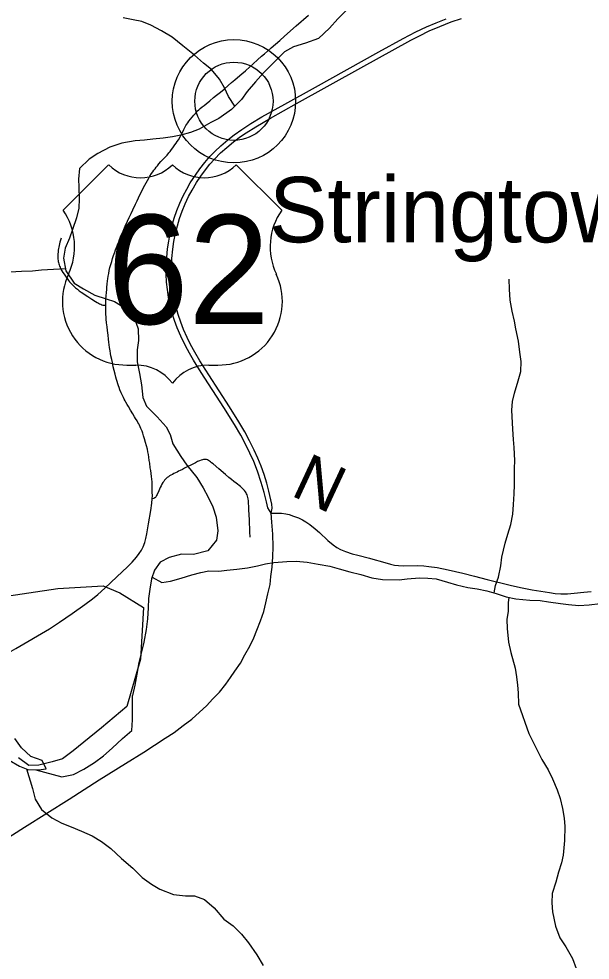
# Model space of a CAD drawing. Extents: x 0 to 34, y 0 to 22.
# Drawn here: x 5.89 to 6.579, y 17.482 to 18.618 of the extents above; entities that cross this region are included whole.
import ezdxf

# ---------------------------------------------------------------- set-up
doc = ezdxf.new("R2010")
doc.units = 0
for name, color, linetype in [('GM_X_Corporation', 7, 'Continuous'), ('GM_X_County_Road', 7, 'Continuous'), ('GM_X_County_Road_Text', 7, 'Continuous'), ('GM_X_Major_River', 7, 'Continuous'), ('GM_X_Minor_River', 7, 'Continuous'), ('GM_X_Township_Road', 7, 'Continuous'), ('GM_X_Unincorporated', 7, 'Continuous'), ('GM_X_Unincorporated_Location', 7, 'Continuous'), ('GM_X_Unincorporated_Text', 7, 'Continuous'), ('GM_X_US_Location', 7, 'Continuous'), ('GM_X_US_Route', 7, 'Continuous'), ('GM_X_US_Shield', 7, 'Continuous')]:
    doc.layers.add(name, color=color, linetype=linetype)

msp = doc.modelspace()

# ---------------------------------------------------------------- linework, layer by layer
at = {"layer": 'GM_X_Corporation'}
msp.add_lwpolyline([(5.6566, 17.8886), (5.9367, 17.9306), (5.9914, 17.934), (6.0115, 17.9254), (6.0403, 17.9078), (6.0367, 17.8455), (6.0202, 17.7883), (5.9894, 17.7625), (5.9681, 17.7452), (5.9552, 17.7349), (5.9426, 17.7251), (5.9299, 17.7214), (5.9138, 17.7172), (5.9017, 17.7169), (5.8892, 17.7264)], dxfattribs=at)
at = {"layer": 'GM_X_County_Road'}
for points in [[(5.9948, 18.2724), (5.9948, 18.2754), (5.9949, 18.2795), (5.9951, 18.2838), (5.9954, 18.2877), (5.9958, 18.2915), (5.996, 18.2943), (5.9964, 18.2981), (5.9968, 18.3018), (5.9971, 18.3045), (5.9976, 18.3077), (5.9982, 18.3109), (5.9989, 18.3146), (5.9996, 18.3179), (6.0007, 18.3217), (6.0018, 18.3253), (6.0029, 18.3289), (6.0041, 18.3325), (6.0055, 18.3364), (6.0065, 18.3393), (6.0075, 18.3423), (6.0087, 18.3455), (6.0102, 18.3492), (6.0113, 18.352), (6.0125, 18.355), (6.0138, 18.3579), (6.0156, 18.362), (6.0182, 18.3679), (6.0208, 18.3738), (6.0229, 18.3784), (6.0251, 18.3831), (6.0273, 18.3876), (6.0305, 18.3943), (6.0324, 18.3983), (6.0342, 18.402), (6.0359, 18.4057), (6.038, 18.4102), (6.0402, 18.4144), (6.0417, 18.4173), (6.0434, 18.4204), (6.0449, 18.4232), (6.0464, 18.4258), (6.048, 18.4284), (6.0499, 18.4315), (6.0513, 18.4334), (6.0527, 18.4355), (6.0541, 18.4372), (6.0555, 18.439), (6.057, 18.4408), (6.0588, 18.443), (6.0612, 18.4458), (6.0632, 18.4481), (6.0662, 18.4514), (6.0686, 18.4538), (6.0709, 18.4564), (6.0724, 18.4582), (6.074, 18.4604), (6.0756, 18.4626), (6.0781, 18.4661), (6.0795, 18.4681), (6.0809, 18.4702), (6.0822, 18.4723), (6.0845, 18.4759), (6.0861, 18.479), (6.0875, 18.4819), (6.0888, 18.4846), (6.0899, 18.4871), (6.0912, 18.4893), (6.0923, 18.4909), (6.0935, 18.4927), (6.0949, 18.4946), (6.097, 18.4971), (6.099, 18.4996), (6.101, 18.502), (6.1028, 18.504), (6.1042, 18.5056), (6.1055, 18.507), (6.1069, 18.5083), (6.1086, 18.5099), (6.1109, 18.5118), (6.1134, 18.5137), (6.1159, 18.5157), (6.1201, 18.5192), (6.1248, 18.5231), (6.1284, 18.526), (6.133, 18.5297), (6.1373, 18.5333), (6.1423, 18.5377), (6.1465, 18.5413), (6.1502, 18.5445), (6.1537, 18.5474), (6.1588, 18.5518), (6.1631, 18.5555), (6.1684, 18.5602), (6.1723, 18.5637), (6.1777, 18.5686), (6.1825, 18.5729), (6.1862, 18.5761), (6.1896, 18.5791), (6.1944, 18.5833), (6.1994, 18.5877), (6.2045, 18.5922), (6.2101, 18.5971), (6.2245, 18.6099), (6.2394, 18.6226)], [(6.0508, 18.0388), (6.0509, 18.0428), (6.0508, 18.0466), (6.0508, 18.0495), (6.0507, 18.0528), (6.0506, 18.0564), (6.0505, 18.0594), (6.0502, 18.0627), (6.0499, 18.0659), (6.0494, 18.0694), (6.0489, 18.0729), (6.0484, 18.0764), (6.0476, 18.0819), (6.0471, 18.0853), (6.0465, 18.0893), (6.046, 18.0923), (6.0454, 18.0957), (6.0448, 18.0988), (6.0438, 18.1028), (6.0426, 18.107), (6.0415, 18.1111), (6.0402, 18.115), (6.0394, 18.1179), (6.0384, 18.1206), (6.0371, 18.1237), (6.0362, 18.1257), (6.0354, 18.1277), (6.0344, 18.1294), (6.0335, 18.131), (6.0324, 18.1328), (6.0307, 18.1357), (6.0293, 18.138), (6.0271, 18.1415), (6.0245, 18.1457), (6.0219, 18.1502), (6.0204, 18.1527), (6.019, 18.1555), (6.018, 18.1572), (6.017, 18.1592), (6.0159, 18.1613), (6.0148, 18.1636), (6.0133, 18.1667), (6.0117, 18.1705), (6.0106, 18.1733), (6.0099, 18.1753), (6.0092, 18.1776), (6.0083, 18.1803), (6.0076, 18.1828), (6.0068, 18.1858), (6.0059, 18.1894), (6.0048, 18.1936), (6.0037, 18.1982), (6.0027, 18.2032), (6.0018, 18.207), (6.0009, 18.2114), (6.0003, 18.2144), (5.9998, 18.2175), (5.9992, 18.2216), (5.9987, 18.2248), (5.9983, 18.228), (5.9979, 18.2316), (5.9974, 18.2365), (5.9967, 18.2421), (5.9962, 18.2463), (5.9957, 18.2513), (5.9953, 18.2555), (5.995, 18.2584), (5.9949, 18.2613), (5.9948, 18.2641), (5.9948, 18.2681), (5.9948, 18.2724)], [(5.9937, 17.9311), (6.008, 17.9449), (6.0207, 17.9567), (6.0263, 17.9623), (6.0317, 17.9683), (6.035, 17.9727), (6.0376, 17.9768), (6.0398, 17.9811), (6.0418, 17.9863), (6.0431, 17.991), (6.0442, 17.9964), (6.0463, 18.0086), (6.0489, 18.0246), (6.0502, 18.0338), (6.0508, 18.0388)], [(6.1941, 18.0214), (6.1983, 18.0215), (6.2005, 18.0216)], [(6.2005, 18.0216), (6.2015, 18.0216), (6.2068, 18.0214), (6.2117, 18.0208), (6.216, 18.0198), (6.2213, 18.0181), (6.2271, 18.0158), (6.2321, 18.0134), (6.2359, 18.0112), (6.241, 18.0077), (6.2474, 18.0028), (6.2524, 17.9982), (6.2624, 17.9886), (6.2691, 17.9832), (6.2736, 17.98), (6.278, 17.9777), (6.2837, 17.9753), (6.292, 17.9726), (6.2986, 17.9707), (6.313, 17.9671), (6.3169, 17.966)], [(6.3169, 17.966), (6.3286, 17.9627), (6.3381, 17.9599), (6.343, 17.9589), (6.3479, 17.9583), (6.3535, 17.958), (6.3709, 17.9582), (6.3783, 17.9579), (6.3845, 17.9573), (6.3943, 17.9558), (6.4077, 17.9532), (6.4253, 17.9492), (6.4397, 17.9455), (6.4548, 17.9416), (6.4825, 17.9347), (6.4952, 17.9318), (6.5092, 17.9291), (6.5301, 17.9256), (6.5369, 17.9247), (6.5437, 17.9243), (6.5517, 17.9243), (6.5598, 17.9248), (6.5715, 17.926), (6.5802, 17.9271)], [(5.8056, 17.8164), (5.8278, 17.8274), (5.8584, 17.8427), (5.8693, 17.8486), (5.886, 17.8583), (5.9268, 17.882), (5.9387, 17.8898), (5.954, 17.9004), (5.9692, 17.9112), (5.9788, 17.9181), (5.985, 17.9232), (5.9937, 17.9311)]]:
    msp.add_lwpolyline(points, dxfattribs=at)
at = {"layer": 'GM_X_Major_River'}
msp.add_lwpolyline([(5.8782, 17.7236), (5.8906, 17.7162), (5.9004, 17.7123), (5.9133, 17.7118), (5.9228, 17.7128), (5.918, 17.7231), (5.9044, 17.7278), (5.8931, 17.7382), (5.8849, 17.7497)], dxfattribs=at)
at = {"layer": 'GM_X_Minor_River'}
for points in [[(6.285, 18.6285), (6.2747, 18.6181), (6.2647, 18.6068), (6.2512, 18.5945), (6.2356, 18.5886), (6.2212, 18.5843)], [(6.1505, 18.5128), (6.1427, 18.5246), (6.1379, 18.5349), (6.1319, 18.5453), (6.1222, 18.5572), (6.1125, 18.5645), (6.1016, 18.5745), (6.0877, 18.5857), (6.0746, 18.5961), (6.0618, 18.6035), (6.049, 18.6105), (6.038, 18.6148), (6.0278, 18.6168), (6.0157, 18.6193)], [(6.2212, 18.5843), (6.2101, 18.5783), (6.1974, 18.5656), (6.1851, 18.5529), (6.1751, 18.542), (6.1651, 18.5304), (6.1586, 18.5206), (6.1463, 18.5087), (6.131, 18.4979), (6.1214, 18.4931), (6.1073, 18.4849), (6.097, 18.4809), (6.0852, 18.4776), (6.075, 18.4759), (6.0639, 18.4741), (6.0514, 18.4728), (6.0415, 18.4718), (6.0302, 18.4708), (6.0142, 18.468), (5.9994, 18.4632), (5.9852, 18.4555), (5.9745, 18.4488), (5.963, 18.4375), (5.9617, 18.4247), (5.962, 18.4148), (5.9626, 18.4008), (5.962, 18.3898), (5.9592, 18.3781), (5.9545, 18.3641), (5.951, 18.3535), (5.9455, 18.3414), (5.9438, 18.3293), (5.9463, 18.3141), (5.9563, 18.2992), (5.9676, 18.2922), (5.9816, 18.2848), (5.9952, 18.2801), (6.005, 18.2769), (6.0196, 18.268), (6.029, 18.2577), (6.0338, 18.2439), (6.0343, 18.2299), (6.0327, 18.2185), (6.0325, 18.2041), (6.0353, 18.1901), (6.0378, 18.1764), (6.0392, 18.1612), (6.0436, 18.1505), (6.0567, 18.1378), (6.0675, 18.1259), (6.0723, 18.1164), (6.0756, 18.1053), (6.0853, 18.09), (6.0923, 18.0793), (6.1047, 18.0644), (6.1121, 18.0521), (6.118, 18.041), (6.1239, 18.0292), (6.1279, 18.0166), (6.13, 18.0003), (6.1284, 17.9889), (6.1176, 17.9762), (6.1005, 17.9715), (6.0861, 17.9721), (6.0712, 17.9681), (6.0602, 17.9626), (6.0536, 17.9528), (6.0497, 17.9422), (6.0476, 17.9297), (6.0463, 17.9187), (6.0458, 17.9074), (6.0449, 17.8941), (6.0432, 17.8812), (6.0404, 17.8657), (6.0372, 17.8525), (6.0347, 17.8412), (6.0323, 17.8272), (6.0299, 17.8139), (6.027, 17.8014)], [(5.9459, 18.3164), (5.9171, 18.3149), (5.9061, 18.3135), (5.8928, 18.3133), (5.8792, 18.3124)], [(6.4631, 17.9252), (6.4647, 17.9343), (6.4686, 17.9445), (6.4714, 17.9578), (6.4727, 17.9684), (6.4767, 17.9854), (6.4799, 17.9963), (6.4835, 18.008), (6.4859, 18.0205), (6.4868, 18.0319), (6.4873, 18.0448), (6.4878, 18.0558), (6.488, 18.0656), (6.4877, 18.0755), (6.4882, 18.085), (6.4873, 18.1009), (6.4866, 18.1104), (6.4857, 18.1229), (6.4844, 18.1457), (6.4853, 18.1563), (6.4877, 18.1665), (6.4921, 18.1812), (6.4953, 18.1926), (6.4958, 18.2047), (6.4944, 18.2157), (6.4927, 18.229), (6.4895, 18.2439), (6.4877, 18.2534), (6.4848, 18.2652), (6.4827, 18.2785), (6.4817, 18.2917), (6.4815, 18.3039)], [(6.0505, 17.9444), (6.0621, 17.9379), (6.0728, 17.9393), (6.0857, 17.9432), (6.0983, 17.9473), (6.1093, 17.9501), (6.1188, 17.9519), (6.1309, 17.9517), (6.1408, 17.9528), (6.1526, 17.9541), (6.1658, 17.9555), (6.1776, 17.9579), (6.1875, 17.9605), (6.1974, 17.9619), (6.2133, 17.9632), (6.2243, 17.9638), (6.2376, 17.9624), (6.2508, 17.96), (6.2648, 17.9575), (6.2762, 17.9543), (6.289, 17.9508), (6.3022, 17.9475), (6.3158, 17.9436), (6.3287, 17.9415), (6.3488, 17.9412), (6.3583, 17.9422), (6.3731, 17.9436), (6.3833, 17.943), (6.3932, 17.9421), (6.4068, 17.9382), (6.4177, 17.935), (6.4313, 17.9318), (6.4427, 17.9301), (6.4544, 17.9277), (6.4657, 17.9245), (6.4778, 17.9205), (6.4895, 17.9181), (6.5062, 17.9167), (6.5187, 17.9162), (6.5289, 17.9145), (6.5433, 17.9124), (6.5531, 17.9115), (6.5656, 17.9102), (6.5781, 17.9108), (6.5911, 17.9125)], [(6.481, 17.9198), (6.48, 17.9137), (6.4802, 17.9034), (6.4786, 17.8932), (6.4788, 17.8822), (6.4805, 17.8659), (6.4834, 17.8533), (6.4885, 17.8343), (6.4902, 17.824), (6.4916, 17.8141), (6.4923, 17.8046), (6.4925, 17.791)], [(5.9102, 17.7119), (5.9418, 17.7032), (5.9555, 17.7061), (5.9681, 17.7124), (5.9811, 17.7205), (5.9919, 17.7287), (6.0023, 17.7381), (6.0149, 17.7497), (6.0261, 17.7594), (6.0269, 17.7723), (6.027, 17.8014)], [(6.4925, 17.791), (6.5053, 17.7558), (6.5127, 17.7405), (6.5208, 17.7244), (6.5285, 17.7117), (6.5337, 17.701), (6.5392, 17.6876), (6.5428, 17.6773), (6.5457, 17.6651), (6.5478, 17.6533), (6.5484, 17.6434), (6.5482, 17.6263), (6.5464, 17.6089), (6.5447, 17.5994), (6.5411, 17.5881), (6.5376, 17.576), (6.5332, 17.5624), (6.533, 17.5514), (6.5336, 17.5403), (6.5372, 17.5232), (6.5427, 17.509), (6.5497, 17.4983), (6.5578, 17.4841), (6.5622, 17.4719)], [(5.8991, 17.7128), (5.9064, 17.6893), (5.9096, 17.6764), (5.917, 17.6637), (5.9297, 17.654), (5.9418, 17.6474), (5.9527, 17.6431), (5.9655, 17.6379), (5.9783, 17.6321), (5.9896, 17.6254), (6.0009, 17.6169), (6.0136, 17.6046), (6.0274, 17.593), (6.0387, 17.5818), (6.0499, 17.5736), (6.0597, 17.5678), (6.0763, 17.5615), (6.091, 17.5597), (6.1017, 17.5596), (6.1137, 17.5552), (6.1253, 17.5452), (6.1369, 17.5317), (6.1485, 17.5236), (6.1586, 17.5136), (6.1668, 17.5028), (6.1768, 17.4886), (6.1846, 17.4756)]]:
    msp.add_lwpolyline(points, dxfattribs=at)
at = {"layer": 'GM_X_Township_Road'}
for points in [[(5.9408, 18.3534), (5.9403, 18.3521), (5.9391, 18.3486), (5.9382, 18.3444), (5.9373, 18.3391), (5.9367, 18.3322), (5.9369, 18.3295), (5.9372, 18.3252), (5.9376, 18.3239), (5.9379, 18.3226), (5.9383, 18.3212), (5.9388, 18.3197), (5.9395, 18.3183), (5.9402, 18.3168), (5.9409, 18.3154), (5.9417, 18.314), (5.9429, 18.3119), (5.9443, 18.3098), (5.9459, 18.3077), (5.948, 18.3049), (5.9498, 18.3025), (5.951, 18.3009), (5.9525, 18.2992), (5.9543, 18.2973), (5.9562, 18.2954), (5.9582, 18.2936), (5.9604, 18.2918), (5.9627, 18.29), (5.9651, 18.2883), (5.973, 18.283), (5.9754, 18.2815), (5.978, 18.2799), (5.9824, 18.2771), (5.9842, 18.2759), (5.9858, 18.275), (5.9872, 18.2742), (5.9886, 18.2736), (5.99, 18.2731), (5.9911, 18.2727), (5.9919, 18.2726), (5.9933, 18.2724), (5.9948, 18.2724)], [(6.1687, 17.9925), (6.1686, 17.9991), (6.1679, 18.0134), (6.1674, 18.0257), (6.1673, 18.0297), (6.167, 18.0335), (6.1667, 18.0365), (6.1664, 18.0389), (6.1661, 18.0406), (6.1657, 18.042), (6.1651, 18.0435), (6.1646, 18.0449), (6.164, 18.0461), (6.1631, 18.0473), (6.162, 18.0488), (6.161, 18.05), (6.1597, 18.0512), (6.1583, 18.0526), (6.157, 18.0537), (6.1518, 18.0579), (6.1491, 18.0598), (6.1463, 18.062), (6.1433, 18.0645), (6.1393, 18.0681), (6.1312, 18.0749), (6.1242, 18.081), (6.1223, 18.0824), (6.121, 18.0834), (6.1196, 18.0845), (6.1186, 18.0851), (6.1174, 18.0859), (6.1163, 18.0862), (6.1153, 18.0864), (6.1144, 18.0864), (6.1135, 18.0864), (6.1125, 18.0863), (6.1112, 18.086), (6.1099, 18.0857), (6.1076, 18.0846), (6.1053, 18.0837), (6.1027, 18.0823), (6.098, 18.08), (6.093, 18.0774), (6.0898, 18.0758), (6.0872, 18.0744), (6.0844, 18.073), (6.0825, 18.0721), (6.0808, 18.0712), (6.0788, 18.0703), (6.0768, 18.0694), (6.075, 18.0684), (6.0732, 18.0675), (6.0717, 18.0666), (6.0702, 18.0655), (6.0689, 18.0645), (6.0678, 18.0636), (6.0666, 18.0624), (6.0656, 18.0614), (6.0645, 18.0599), (6.0635, 18.0584), (6.0623, 18.0565), (6.0613, 18.0546), (6.0603, 18.0525), (6.0585, 18.0486), (6.0565, 18.0442), (6.0559, 18.0429), (6.0546, 18.0406), (6.0539, 18.0399), (6.0528, 18.0394), (6.0508, 18.0388)]]:
    msp.add_lwpolyline(points, dxfattribs=at)
at = {"layer": 'GM_X_Unincorporated'}
for radius in [0.0744, 0.0472]:
    msp.add_circle((6.1493, 18.5187), radius, dxfattribs=at)
at = {"layer": 'GM_X_Unincorporated_Location'}
msp.add_line((6.1493, 18.5187), (6.1493, 18.5187), dxfattribs=at)
at = {"layer": 'GM_X_US_Route'}
for points in [[(6.1941, 18.0214), (6.1901, 18.0278), (6.1887, 18.0352), (6.1857, 18.0466), (6.1822, 18.0586), (6.1776, 18.0721), (6.1731, 18.0838), (6.1686, 18.0941), (6.1637, 18.1041), (6.1575, 18.1156), (6.1499, 18.1285), (6.137, 18.1491), (6.1096, 18.1913), (6.1004, 18.206), (6.0955, 18.2146), (6.0908, 18.2234), (6.0852, 18.2351), (6.0808, 18.2453), (6.0776, 18.254), (6.0748, 18.2629), (6.0723, 18.2724), (6.0703, 18.2821), (6.069, 18.2913), (6.0681, 18.3005), (6.0677, 18.3098), (6.0678, 18.3203), (6.0683, 18.3302), (6.0693, 18.3407), (6.0707, 18.3498), (6.0725, 18.3596), (6.0748, 18.3692), (6.0772, 18.3775), (6.0804, 18.3869), (6.0839, 18.3955), (6.088, 18.4045), (6.0923, 18.4127), (6.0966, 18.4202), (6.1027, 18.4295), (6.1081, 18.4371), (6.1142, 18.4449), (6.1203, 18.4519), (6.1262, 18.4581), (6.1334, 18.465), (6.1418, 18.4722), (6.1497, 18.4782), (6.1588, 18.4846), (6.1697, 18.4917), (6.183, 18.4997), (6.2106, 18.5152), (6.2476, 18.5356), (6.3242, 18.5782), (6.3535, 18.5943), (6.3689, 18.6024), (6.3818, 18.6085), (6.3931, 18.6135), (6.4052, 18.6183)], [(6.1941, 18.0214), (6.1954, 18.0277), (6.195, 18.0324), (6.1915, 18.0482), (6.1889, 18.0577), (6.1856, 18.0683), (6.182, 18.0782), (6.1781, 18.088), (6.1737, 18.0976), (6.1682, 18.1087), (6.1623, 18.1196), (6.155, 18.1318), (6.1438, 18.1497), (6.119, 18.1884), (6.1083, 18.2052), (6.1019, 18.2159), (6.0969, 18.2252), (6.0927, 18.2336), (6.0885, 18.2433), (6.0851, 18.2521), (6.082, 18.2615), (6.0793, 18.2718), (6.0775, 18.2804), (6.0758, 18.2909), (6.0748, 18.3008), (6.0742, 18.3101), (6.0741, 18.3207), (6.0745, 18.3289), (6.0755, 18.34), (6.0768, 18.3493), (6.0787, 18.3591), (6.081, 18.3682), (6.0836, 18.3772), (6.0868, 18.386), (6.0903, 18.3947), (6.0946, 18.4037), (6.0987, 18.4114), (6.1041, 18.4206), (6.1093, 18.4284), (6.1148, 18.4359), (6.1203, 18.4427), (6.1257, 18.4488), (6.1332, 18.4563), (6.1406, 18.4629), (6.1488, 18.4697), (6.1573, 18.476), (6.164, 18.4806), (6.1756, 18.488), (6.1933, 18.4983), (6.2247, 18.516), (6.3024, 18.559), (6.3628, 18.5923), (6.3733, 18.5978), (6.385, 18.6035), (6.3976, 18.609), (6.4115, 18.6144), (6.4239, 18.6187)], [(5.8617, 17.6205), (5.8966, 17.6427), (5.9504, 17.6763), (5.9868, 17.6995), (6.0185, 17.7193), (6.0404, 17.733), (6.0665, 17.7499), (6.0772, 17.7567), (6.088, 17.7651), (6.0985, 17.7729), (6.1079, 17.7813), (6.1163, 17.7892), (6.124, 17.7973), (6.1319, 17.8056), (6.1395, 17.8151), (6.145, 17.8232), (6.1503, 17.8309), (6.157, 17.8404), (6.1626, 17.8504), (6.1683, 17.8611), (6.1731, 17.871), (6.1768, 17.8804), (6.1814, 17.8916), (6.1854, 17.903), (6.1878, 17.9133), (6.1902, 17.9241), (6.1928, 17.9355), (6.1939, 17.9451), (6.1955, 17.9563), (6.1963, 17.969), (6.1966, 17.9809), (6.1964, 17.9961), (6.195, 18.0106), (6.1941, 18.0214)]]:
    msp.add_lwpolyline(points, dxfattribs=at)
at = {"layer": 'GM_X_US_Shield'}
for p, q in [((5.9981, 18.442), (5.9432, 18.3871)), ((6.2069, 18.3871), (6.1519, 18.442)), ((6.0201, 18.2003), (6.0311, 18.2003)), ((6.119, 18.2003), (6.13, 18.2003))]:
    msp.add_line(p, q, dxfattribs=at)
for centre, radius, start, end in [((6.0366, 18.4812), 0.0549, 225.573, 314.427), ((6.1135, 18.4812), 0.0549, 225.573, 314.427), ((5.8802, 18.343), 0.0769, 334.5471, 35.0009), ((6.2699, 18.343), 0.0769, 144.9991, 205.4529), ((6.0192, 18.2772), 0.0769, 154.8319, 270.6383), ((6.1308, 18.2772), 0.0769, 269.3617, 25.1681), ((6.0311, 18.1454), 0.0549, 36.8699, 90), ((6.119, 18.1454), 0.0549, 90, 143.1301)]:
    msp.add_arc(centre, radius, start, end, dxfattribs=at)

# ---------------------------------------------------------------- texts
at = {"layer": 'GM_X_County_Road_Text'}
msp.add_text('N', height=0.0568, rotation=335.0577, dxfattribs=at).set_placement((6.2163, 18.0436))
at = {"layer": 'GM_X_Unincorporated_Text'}
msp.add_text('Stringtown', height=0.07898, rotation=0, dxfattribs=at).set_placement((6.1917, 18.3484))
at = {"layer": 'GM_X_US_Location'}
for s in ['0', '/']:
    msp.add_text(s, height=0.000189, dxfattribs=at).set_placement((6.075, 18.3146))
msp.add_text('62', height=0.000189, rotation=0, dxfattribs=at).set_placement((6.0359, 18.2754))
at = {"layer": 'GM_X_US_Shield'}
msp.add_text('62', height=0.13184, dxfattribs=at).set_placement((5.9963, 18.2498))

doc.saveas('drawing.dxf')
